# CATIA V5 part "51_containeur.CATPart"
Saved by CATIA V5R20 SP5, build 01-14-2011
Part number: 51_containeur
Bounding box of the stored display mesh (mm): x -78 to 78, y 62.362 to 218.362, z -20.576 to 169.224
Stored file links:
  C:\Documents and Settings\anizard\Bureau\13\51_containeur.CATPart
  C:\Documents and Settings\anizard\Bureau\13\anizard.CATProduct
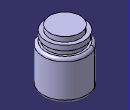
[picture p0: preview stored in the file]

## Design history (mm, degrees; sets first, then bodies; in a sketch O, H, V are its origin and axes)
External parameters (linked from other documents)
  External.diametre = 156 mm
Set1
  Plane1 to Plane3: linked copy from another document
  Line1: linked copy from another document
Body1 (main body)
  Sketch1 on Plane1, origin (0, 0, 0), H (0, 1, 0), V (0, 0, 1)
    line L1 (140.3619, 169.2244) -> (194.3619, 169.2244)
    line L2 (194.3619, 169.2244) -> (194.3619, 152.2244)
    line L3 (194.3619, 152.2244) -> (208.3619, 152.2244)
    line L4 (208.3619, 152.2244) -> (208.3619, 135.2244)
    line L5 (208.3619, 135.2244) -> (201.3619, 135.2244)
    line L6 (201.3619, 135.2244) -> (201.3619, 118.2244)
    line L7 (201.3619, 118.2244) -> (208.3619, 118.2244)
    line L8 (218.3619, 108.2244) -> (218.3619, -10.5756)
    line L9 (208.3619, -20.5756) -> (140.3619, -20.5756)
    line L10 (140.3619, -20.5756) -> (140.3619, 169.2244)
    reference projected line E1 (140.3619, -190) -> (140.3619, 190) from Line1
    arc A1 centre (208.3619, 108.2244) radius 10 from (208.3619, 118.2244) to (218.3619, 108.2244) cw
    arc A2 centre (208.3619, -10.5756) radius 10 from (218.3619, -10.5756) to (208.3619, -20.5756) cw
    reference intersected line E2 through (0, -20.6756) direction (-1, 0) from Plane3
    reference intersected line E3 through (0, 169.3244) direction (-1, 0) from Plane2
    distance L10 L8 = 78 {= External.diametre /2}
    distance L6 L8 = 17
    distance L6 L4 = 7
    distance L2 L4 = 14
    distance L7 L5 = 17
    distance L3 L5 = 17
    distance L3 L1 = 17
    radius A1 = 10
    radius A2 = 10
    distance L9 E2 = 0.1
    distance E3 L1 = 0.1
    horizontal: L1 H, L3 H, L5 H, L7 H, L9 H
    vertical: L2 V, L4 V, L6 V, L8 V, L10 V
    coincidence: L10 E1
    tangency: A1 L7, A1 L8, A2 L8, A2 L9
  Shaft1: profile Sketch1, axis Line1, angle 360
